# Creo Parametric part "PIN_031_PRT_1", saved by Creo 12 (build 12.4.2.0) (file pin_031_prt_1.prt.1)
Units: Custom; MM, KILOGRAM, SECS

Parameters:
  PTC_WM_ITERATION = "0"
  PTC_WM_VERSION = "-.0"
  PTC_WM_LIFECYCLE_STATE = "In Work"
  PTC_WM_LIFECYCLE = "MO_CADDocument"
  PTC_WM_CREATED_BY = "Maximilian Roepper (Z0017RMS: MO)"
  PTC_WM_CREATED_ON = "18-Sep-26 11:36:42 AM"
  PTC_WM_MODIFIED_BY = "Maximilian Roepper (Z0017RMS: MO)"
  PTC_WM_MODIFIED_ON = "18-Sep-26 11:36:46 AM"
  PDMLINKNUMBER = "PDM000071455074"
  PTC_WM_NAME = "pin_031_prt_1.prt"
  PTC_WM_NUMBER = "PDM000071455074"

Other parameters: WEIGHT, WEIGHT_FACTOR, WEIGHT_ADD, _MASS_TEMP, _DIFF_TEMP, MC_ERRORS, SUPPLIER

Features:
  1. coordinate system
  2. datum plane "PRT_YZ"
  3. datum plane "PRT_XY"
  4. datum plane "PRT_XZ"
  5. coordinate system
  6. datum axis
  7. datum axis
  8. datum axis
  9. coordinate system
  10. imported feature
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
Other named items: PRT, SIEMENS_MO, DRW_VIEW_ORG, PRT_X, PRT_Y, PRT_Z, CS0, ROUGH_GROB

Layers: 00_STD_CSYS-KSYS, 01_STD_PLANES-EBENEN, 02_STD_AXES-ACHSEN, 03_STD_CSYS-KSYS, 24_IMPORT_FEAT-IMPORT_KE

Surfaces: 9 plane, 1 cylinder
